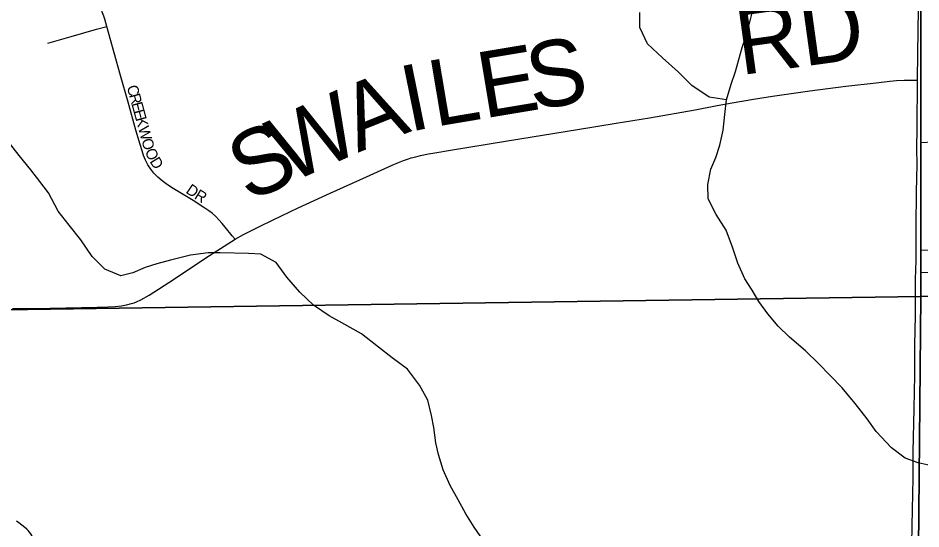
# Model space of a CAD drawing. Extents: x 0 to 680, y 0 to 440.
# Drawn here: x 476.22 to 489.89, y 291.9 to 299.64 of the extents above; entities that cross this region are included whole.
import ezdxf

# ---------------------------------------------------------------- set-up
doc = ezdxf.new("R2010")
doc.units = 0
for name, color, linetype in [('GM_X_Corporation', 7, 'Continuous'), ('GM_X_County_Road', 7, 'Continuous'), ('GM_X_County_Road_Text', 7, 'Continuous'), ('GM_X_Minor_River', 7, 'Continuous'), ('GM_X_Section', 7, 'Continuous'), ('GM_X_Township_Subdivision', 7, 'Continuous'), ('GM_X_Township_Subdivision_Text', 7, 'Continuous')]:
    doc.layers.add(name, color=color, linetype=linetype)

msp = doc.modelspace()

# ---------------------------------------------------------------- linework, layer by layer
at = {"layer": 'GM_X_Corporation'}
for points in [[(490.072, 296.124), (489.886, 296.117), (489.886, 297.756), (490.072, 297.763)], [(489.888, 295.518), (489.886, 295.784), (490.072, 295.79)]]:
    msp.add_lwpolyline(points, dxfattribs=at)
at = {"layer": 'GM_X_County_Road'}
for points in [[(489.836, 298.7), (489.841, 299.109), (489.857, 300.434), (489.871, 301.234), (489.87, 301.529), (489.885, 302.635), (489.893, 303.204), (489.893, 303.25), (489.899, 303.982), (489.897, 305.176)], [(479.504, 296.289), (479.505, 296.29), (479.629, 296.36), (479.873, 296.484), (480.081, 296.582), (480.456, 296.763), (480.943, 296.989), (481.492, 297.236), (481.882, 297.412), (481.979, 297.452), (482.055, 297.483), (482.112, 297.502), (482.17, 297.521), (482.238, 297.539), (482.309, 297.556), (482.431, 297.581), (482.525, 297.597), (482.763, 297.636), (483.627, 297.778), (484.687, 297.952), (485.27, 298.047), (485.778, 298.128), (486.468, 298.247), (486.801, 298.314), (487.027, 298.356), (487.352, 298.408), (487.639, 298.453), (488.206, 298.535), (488.749, 298.605), (489.206, 298.659), (489.414, 298.682), (489.514, 298.691), (489.632, 298.7), (489.759, 298.7), (489.836, 298.7)], [(489.813, 296.31), (489.812, 296.482), (489.818, 297.007), (489.827, 297.423), (489.825, 297.664), (489.828, 297.971), (489.836, 298.7)], [(476.136, 295.241), (476.467, 295.243), (477.416, 295.259), (477.578, 295.265), (477.687, 295.272), (477.783, 295.283), (477.86, 295.297), (477.934, 295.314), (477.976, 295.327), (478.011, 295.344), (478.079, 295.374), (478.203, 295.44), (478.57, 295.679), (478.88, 295.886), (479.116, 296.044), (479.392, 296.221), (479.504, 296.289)], [(489.811, 295.966), (489.813, 296.033), (489.813, 296.31)], [(489.802, 295.435), (489.804, 295.683), (489.811, 295.966)], [(489.737, 291.082), (489.738, 291.131), (489.752, 291.952), (489.766, 292.675), (489.77, 293.069), (489.781, 293.725), (489.792, 294.229), (489.791, 294.547), (489.793, 294.689), (489.802, 295.127), (489.802, 295.281), (489.802, 295.435)]]:
    msp.add_lwpolyline(points, dxfattribs=at)
at = {"layer": 'GM_X_Minor_River'}
for points in [[(490.117, 292.843), (489.844, 292.903), (489.645, 292.974), (489.442, 293.133), (489.207, 293.379), (489.071, 293.569), (488.889, 293.801), (488.694, 294.039), (488.511, 294.224), (488.334, 294.409), (488.138, 294.601), (487.895, 294.807), (487.725, 294.972), (487.569, 295.162), (487.433, 295.346), (487.33, 295.516), (487.22, 295.692), (487.112, 295.929), (487.031, 296.171), (486.936, 296.428), (486.788, 296.665), (486.667, 296.902), (486.658, 297.116), (486.704, 297.349), (486.781, 297.528), (486.839, 297.714), (486.891, 297.94), (486.917, 298.18), (486.942, 298.4), (487.014, 298.639), (487.079, 298.831), (487.181, 299.19), (487.253, 299.422), (487.304, 299.615), (487.371, 299.881)], [(486.942, 298.4), (486.682, 298.439), (486.419, 298.619), (486.209, 298.825), (485.974, 299.038), (485.745, 299.25), (485.63, 299.494), (485.628, 299.721)], [(478.143, 295.862), (477.954, 295.78), (477.772, 295.737), (477.534, 295.836), (477.338, 296.028), (477.17, 296.279), (476.994, 296.504), (476.825, 296.715), (476.678, 296.993), (476.548, 297.163), (476.412, 297.34), (476.236, 297.558), (476.054, 297.79)], [(483.296, 291.684), (483.121, 291.929), (482.999, 292.133), (482.883, 292.343), (482.761, 292.559), (482.653, 292.796), (482.585, 293.032), (482.542, 293.206), (482.514, 293.441), (482.478, 293.622), (482.423, 293.851), (482.295, 294.081), (482.113, 294.32), (481.883, 294.492), (481.673, 294.657), (481.417, 294.857), (481.12, 295.025), (480.928, 295.129), (480.691, 295.289), (480.482, 295.487), (480.286, 295.713), (480.124, 295.937), (479.893, 296.063), (479.706, 296.074), (479.278, 296.084), (479.098, 296.081), (478.83, 296.047), (478.527, 295.974), (478.318, 295.919), (478.143, 295.862)]]:
    msp.add_lwpolyline(points, dxfattribs=at)
at = {"layer": 'GM_X_Section'}
for points in [[(497.798, 295.599), (489.884, 295.42), (489.874, 313.088), (504.362, 313.265)], [(504.647, 277.105), (489.711, 276.904), (489.884, 295.42), (497.798, 295.599)]]:
    msp.add_lwpolyline(points, dxfattribs=at)
for points in [[(489.874, 313.088), (489.884, 295.42), (471.851, 295.162), (471.837, 312.991)], [(471.851, 295.162), (489.884, 295.42), (489.711, 276.904), (471.85, 277.333)]]:
    msp.add_lwpolyline(points, close=True, dxfattribs=at)
at = {"layer": 'GM_X_Township_Subdivision'}
for points in [[(477.562, 299.512), (477.531, 299.621), (477.515, 299.668), (477.499, 299.718), (477.483, 299.759), (477.467, 299.795), (477.45, 299.833), (477.426, 299.873), (477.402, 299.914)], [(476.67, 299.26), (477.02, 299.359), (477.407, 299.468), (477.562, 299.512)], [(479.504, 296.289), (479.461, 296.342), (479.355, 296.472), (479.307, 296.53), (479.259, 296.585), (479.21, 296.635), (479.161, 296.678), (479.104, 296.721), (479.046, 296.762), (478.871, 296.874), (478.541, 297.075), (478.46, 297.127), (478.398, 297.173), (478.334, 297.229), (478.276, 297.289), (478.227, 297.349), (478.185, 297.416), (478.149, 297.486), (478.119, 297.558), (478.096, 297.626), (478.066, 297.722), (478.001, 297.941), (477.884, 298.364), (477.769, 298.766), (477.674, 299.111), (477.562, 299.512)], [(476.496, 291.058), (476.494, 291.412), (476.494, 291.499), (476.492, 291.551), (476.49, 291.59), (476.484, 291.628), (476.478, 291.655), (476.469, 291.689), (476.461, 291.719), (476.45, 291.746), (476.439, 291.774), (476.426, 291.803), (476.411, 291.828), (476.393, 291.852), (476.371, 291.877), (476.349, 291.899), (476.323, 291.925), (476.278, 291.961), (476.23, 291.996), (476.194, 292.023)]]:
    msp.add_lwpolyline(points, dxfattribs=at)

# ---------------------------------------------------------------- texts
at = {"layer": 'GM_X_County_Road_Text'}
for s, height, rotation, p in [('RD', 1.0014, 7.8541, (487.156, 298.773)), ('S', 1.001, 9.4654, (484.005, 298.239)), ('E', 1.001, 9.4673, (483.266, 298.116)), ('I', 1.001, 11.489, (482.134, 297.911)), ('L', 1.001, 9.5673, (482.528, 297.991)), ('A', 1.001, 21.7635, (481.361, 297.598)), ('W', 1.001, 24.3993, (480.315, 297.123)), ('S', 1.001, 24.4247, (479.7, 296.844))]:
    msp.add_text(s, height=height, rotation=rotation, dxfattribs=at).set_placement(p)
at = {"layer": 'GM_X_Township_Subdivision_Text'}
for s, rotation, p in [('C', 285.3616, (477.862, 298.598)), ('R', 285.3616, (477.897, 298.471)), ('E', 285.3486, (477.932, 298.343)), ('E', 285.3447, (477.963, 298.23)), ('K', 285.3512, (477.995, 298.117)), ('W', 285.359, (478.033, 297.975)), ('O', 285.351, (478.084, 297.791)), ('O', 294.5458, (478.133, 297.622)), ('D', 301.741, (478.205, 297.468)), ('D', 325.6007, (478.746, 297)), ('R', 328.673, (478.875, 296.912))]:
    msp.add_text(s, height=0.167, rotation=rotation, dxfattribs=at).set_placement(p)

doc.saveas('drawing.dxf')
